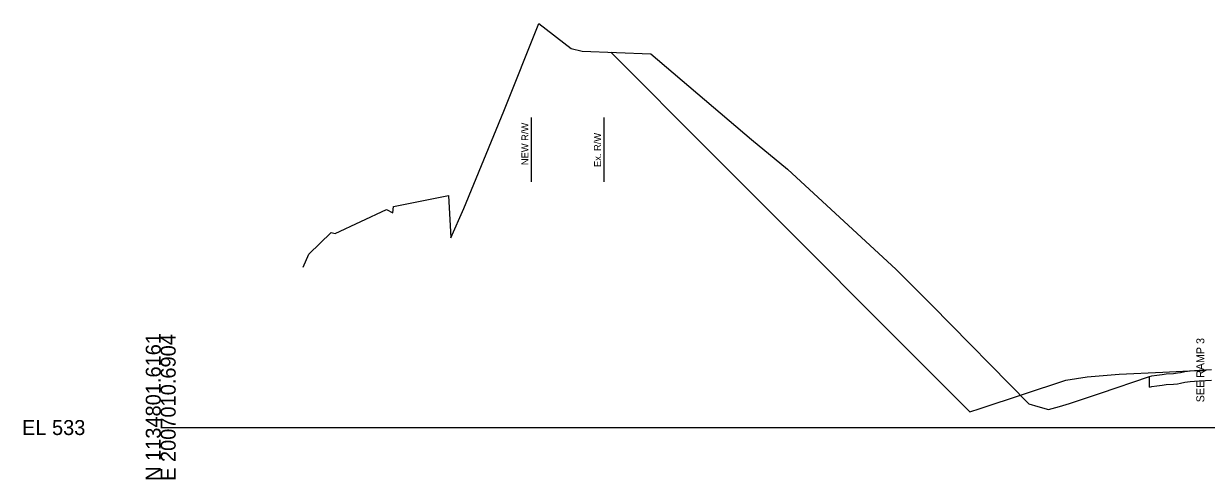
# Model space of a CAD drawing. Extents: x -201 to 2007062, y -213 to 1139737.
# Drawn here: x 974.3 to 1196, y 1990.3 to 2075.6 of the extents above; entities that cross this region are included whole.
import ezdxf

# ---------------------------------------------------------------- set-up
doc = ezdxf.new("R2010")
doc.units = 0
for name, color, linetype in [('Default', 7, 'Continuous'), ('RD_DTM_Design_FG', 7, 'Continuous'), ('RD_GPK_XS_Cell', 7, 'Continuous'), ('RD_XS_ExGround', 7, 'Continuous'), ('RD_XS_ExPaveRet', 7, 'Continuous'), ('RD_XS_ExRW', 7, 'Continuous'), ('RD_XS_NewRW', 7, 'Continuous'), ('RD_XS_SideStreet', 7, 'Continuous')]:
    doc.layers.add(name, color=color, linetype=linetype)

msp = doc.modelspace()

# ---------------------------------------------------------------- linework, layer by layer
at = {"layer": 'RD_DTM_Design_FG'}
msp.add_lwpolyline([(1084.36, 2070.24), (1103.04, 2051.55), (1151.64, 2002.91), (1153.61, 2003.56), (1169.65, 2008.88), (1173.65, 2009.51), (1179.66, 2009.98), (1187.83, 2010.37), (1194.09, 2010.67), (1194.57, 2010.68), (1195.67, 2010.59), (1196, 2010.79)], dxfattribs=at)
at = {"layer": 'RD_GPK_XS_Cell'}
msp.add_line((1000, 2000), (1250, 2000), dxfattribs=at)
at = {"layer": 'RD_XS_ExGround'}
msp.add_lwpolyline([(1026.68, 2030.01), (1027.78, 2032.45), (1031.98, 2036.48), (1032.73, 2036.35), (1042.31, 2040.8), (1043.5, 2040.21), (1043.61, 2041.4), (1045.17, 2041.7), (1053.92, 2043.42), (1054.39, 2035.53), (1056.83, 2041.03), (1064.32, 2059.2), (1070.9, 2075.6), (1076.93, 2070.93), (1079.01, 2070.43), (1091.9, 2069.97), (1110.72, 2053.94), (1117.49, 2048.38), (1137.84, 2029.58), (1140.76, 2026.72), (1144.53, 2022.9), (1162.73, 2004.43), (1164.43, 2003.92), (1166.39, 2003.35), (1168.5, 2003.95), (1170.36, 2004.5), (1176.19, 2006.44), (1185.37, 2009.58), (1185.8, 2009.66), (1186.72, 2009.82), (1187.75, 2009.95), (1188.48, 2010.04), (1189.86, 2010.14), (1190.6, 2010.21), (1191.14, 2010.29), (1191.97, 2010.5), (1192.99, 2010.6), (1193.75, 2010.66), (1194.68, 2010.72), (1195.28, 2010.75), (1195.84, 2010.79), (1196.97, 2010.88)], dxfattribs=at)
at = {"layer": 'RD_XS_ExPaveRet'}
for p, q in [((1185.37, 2007.58), (1185.37, 2009.58)), ((1191.97, 2008.5), (1192.99, 2008.6)), ((1192.99, 2008.6), (1193.75, 2008.66)), ((1193.75, 2008.66), (1194.68, 2008.72)), ((1194.68, 2008.72), (1195.28, 2008.75)), ((1195.28, 2008.75), (1195.84, 2008.79)), ((1195.84, 2008.79), (1196.97, 2008.88)), ((1185.37, 2007.58), (1185.8, 2007.66)), ((1185.8, 2007.66), (1186.72, 2007.82)), ((1186.72, 2007.82), (1187.75, 2007.95)), ((1187.75, 2007.95), (1188.48, 2008.04)), ((1188.48, 2008.04), (1189.86, 2008.14)), ((1189.86, 2008.14), (1190.6, 2008.21)), ((1190.6, 2008.21), (1191.14, 2008.29)), ((1191.14, 2008.29), (1191.97, 2008.5))]:
    msp.add_line(p, q, dxfattribs=at)
at = {"layer": 'RD_XS_ExRW'}
msp.add_line((1083.03, 2058.01), (1083.03, 2046.01), dxfattribs=at)
at = {"layer": 'RD_XS_NewRW'}
msp.add_line((1069.45, 2058.01), (1069.45, 2046.01), dxfattribs=at)

# ---------------------------------------------------------------- texts
at = {"layer": 'Default'}
msp.add_text('-', height=0.0001, dxfattribs=at).set_placement((1000, 2000))
at = {"layer": 'RD_GPK_XS_Cell'}
for s, p in [('N 1134801.6161', (1000, 1990)), ('E 2007010.6904', (1002.8, 1990))]:
    msp.add_text(s, height=2.8, rotation=90, dxfattribs=at).set_placement(p)
msp.add_text('EL 533', height=2.8, dxfattribs=at).set_placement((974, 1998.6))
at = {"layer": 'RD_XS_ExRW'}
msp.add_text('Ex. R/W ', height=1.3, rotation=90, dxfattribs=at).set_placement((1082.53, 2048.78))
at = {"layer": 'RD_XS_NewRW'}
msp.add_text('NEW R/W ', height=1.3, rotation=90, dxfattribs=at).set_placement((1068.92, 2049.13))
at = {"layer": 'RD_XS_SideStreet'}
msp.add_text('SEE RAMP 3', height=1.5, rotation=90, dxfattribs=at).set_placement((1195.62, 2004.72))

doc.saveas('drawing.dxf')
